(* Logix 5000 project; controller NXFE2_EDS_AOI_sample_RSLogix_V31 vendor 1 type 14 code 92 rev 31.11; software revision 31.00; part 4 of 4 *)

ADD_ON_INSTRUCTION AMCI_NXFE2_Set_State   (* revision 1.0, vendor AMCI, ExecuteEnableInFalse *)
VAR_INPUT
   axis_status_bits : INT; {required}
   No_Fault_Output_0_OFF_1_ON : BOOL; {required}
   On_Line_Output_0_OFF_1_ON : BOOL; {required}
   Move_Complete_Output_0_OFF_1_ON : BOOL; {required}
END_VAR
VAR_IN_OUT
   NXFE2_output_data : _000A:NXFE2_0986AEB4:O:0; {required}
END_VAR
VAR_OUTPUT
   EN : BOOL; {access Read Only, visible}
   ER : BOOL; {access Read Only, visible}
END_VAR
VAR
   command_data_block : INT[10];
        [1]   // Command Bits LSW
        [3]   // Lower Target Position
        [5]   // Lower Programmed Speed
        [1].5   // set state bit
        [0]   // Command Bits MSW
        [2]   // Upper Target Position
        [4]   // Upper Programmed Speed
END_VAR

ROUTINE EnableInFalse   (* ladder *)
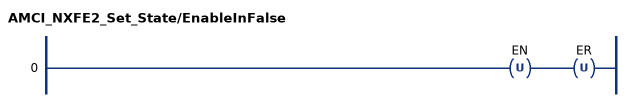
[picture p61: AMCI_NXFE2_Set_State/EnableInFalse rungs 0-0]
   0: OTU(EN)OTU(ER);
END_ROUTINE

ROUTINE Logic   (* ladder *)
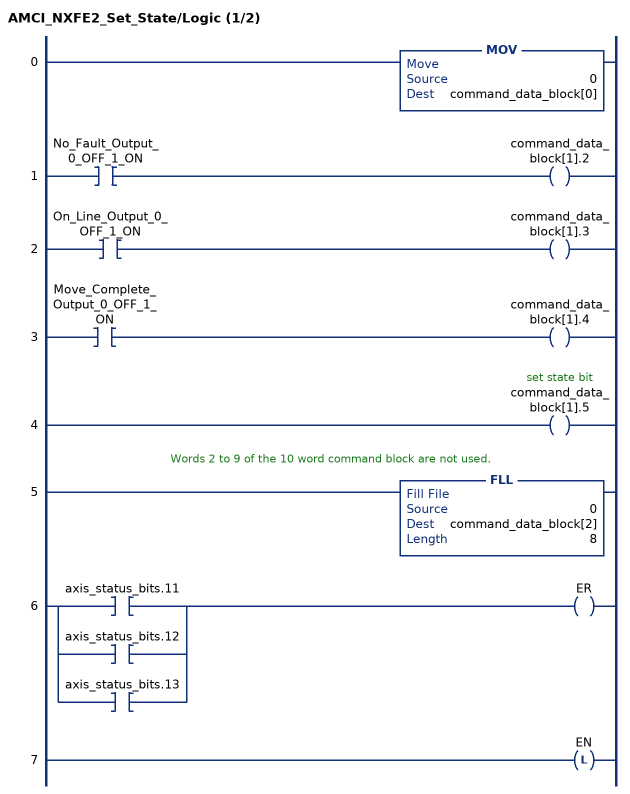
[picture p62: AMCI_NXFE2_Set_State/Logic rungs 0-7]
   0: MOV(0,command_data_block[0]);
   1: XIC(No_Fault_Output_0_OFF_1_ON)OTE(command_data_block[1].2);
   2: XIC(On_Line_Output_0_OFF_1_ON)OTE(command_data_block[1].3);
   3: XIC(Move_Complete_Output_0_OFF_1_ON)OTE(command_data_block[1].4);
   4: OTE(command_data_block[1].5);
   // Words 2 to 9 of the 10 word command block are not used.
   5: FLL(0,command_data_block[2],8);
   6: [XIC(axis_status_bits.11) ,XIC(axis_status_bits.12) ,XIC(axis_status_bits.13) ]OTE(ER);
   7: OTL(EN);
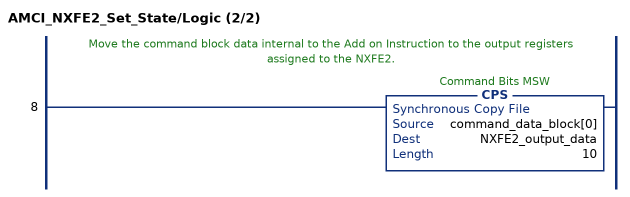
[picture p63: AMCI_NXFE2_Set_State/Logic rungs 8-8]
   // Move the command block data internal to the Add on Instruction to the output registers assigned to the NXFE2.
   8: CPS(command_data_block[0],NXFE2_output_data,10);
END_ROUTINE
END_ADD_ON_INSTRUCTION

VAR_GLOBAL   (* controller tags *)
   buffered_NXFE2_data : INT[10];
        [0].9   // set when the SD17060E is ready to receive a blend move segment
        [0].14   // AMCI ANG1E OK bit
        [0].15   // AMCI NXFE2 mode bit 1=config mode 0=command mode
        [1].15   // AMCI ANG1E set when driver enabled
        [0].0   // AMCI ANG1E motion occuring CW
        [0].1   // AMCI ANG1E motion occuring CCW
        [0].7   // ANG1E Move Compete bit
        [0].8   // set when SD17060E is in blend move mode
        [1].7   // AMCI ANG1E set when driver fault
        [0].10   // AMCI NXFE2 position invalid bit
        [0].13   // AMCI NXFE2 configuration error
   comment : INT;   // used as output instruction on comment rungs
   NXFE2_Communication_Status : INT;
   run_NXFE2 : INT;   // 1=absolute move 2=relative move 3=CW jog 4=CCW jog 5=Reset errors 6=Home CW 7=Preset Position 8=Program Blend 9=Run Blend
END_VAR

PROGRAM MainProgram   (* main routine MainRoutine *)
VAR
   AMCI_NXFE2_Set_State_AOI : AMCI_NXFE2_Set_State;
   NXFE2_Absolute_AOI : AMCI_NXFE2_Absolute_Move;
   NXFE2_Absolute_Move_AOI : AMCI_NXFE2_Absolute_Move;
   NXFE2_Configure_AOI : AMCI_NXFE2_Configure;
   NXFE2_encoder_follower_CCW : AMCI_NXFE2_Encoder_Follower_CCW;
   NXFE2_encoder_follower_CW : AMCI_NXFE2_Encoder_Follower_CW;
   NXFE2_Hold_AOI : AMCI_NXFE2_Hold;
   NXFE2_Home_CCW_AOI : AMCI_NXFE2_Home_CCW;
   NXFE2_Home_CW_AOI : AMCI_NXFE2_Home_CW;
   NXFE2_Immediate_Stop_AOI : AMCI_NXFE2_Immediate_Stop;
   NXFE2_Jog_CCW_AOI : AMCI_NXFE2_Jog_CCW;
   NXFE2_Jog_CW_AOI : AMCI_NXFE2_Jog_CW;
   NXFE2_Min_Registration_Distance_AOI : AMCI_NXFE2_Minimum_Registration_Distance;
   NXFE2_Preset_encoder_AOI : AMCI_NXFE2_Preset_Encoder_Position;
   NXFE2_Preset_Position_AOI : AMCI_NXFE2_Preset_Position;
   NXFE2_Program_Blend_AOI : AMCI_NXFE2_Program_Blend_Move;
   NXFE2_Registration_CCW_AOI : AMCI_NXFE2_Registration_Move_CCW;
   NXFE2_Registration_CW_AOI : AMCI_NXFE2_Registration_Move_CW;
   NXFE2_Relative_Move_AOI : AMCI_NXFE2_Relative_Move;
   NXFE2_Reset_Errors_AOI : AMCI_NXFE2_Reset_Errors;
   NXFE2_Resume_AOI : AMCI_NXFE2_Resume;
   NXFE2_Run_Blend : AMCI_NXFE2_Run_Blend_Move;
END_VAR

ROUTINE Blend_Move   (* ladder *)
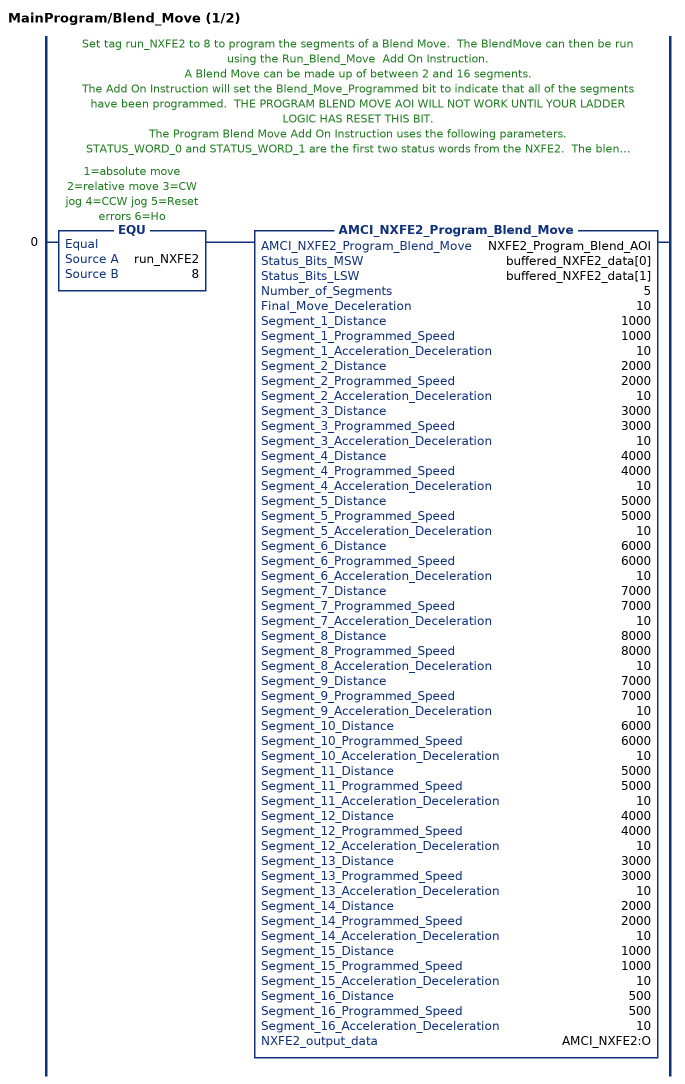
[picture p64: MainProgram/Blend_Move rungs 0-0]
   // Set tag run_NXFE2 to 8 to program the segments of a Blend Move.  The BlendMove can then be run using the Run_Blend_Move  Add On Instruction.
   // A Blend Move can be made up of between 2 and 16 segments.
   // The Add On Instruction will set the Blend_Move_Programmed bit to indicate that all of the segments have been programmed.  THE PROGRAM BLEND MOVE AOI WILL NOT WORK UNTIL YOUR LADDER LOGIC HAS RESET THIS BIT.
   // The Program Blend Move Add On Instruction uses the following parameters.
   // STATUS_WORD_0 and STATUS_WORD_1 are the first two status words from the NXFE2.  The blend move will not be correctly programmed if these two status words are not correctly brought into the program blend add on instruction.
   // NUMBER OF SEGMENTS: An actual value or an INT type register that has a range of 2 to 16 and specifies the number of segments of the Blend Move.
   // SEGMENT_X_DISTANCE: An actual value or a DINT type register.  The relative distance of each of the Blend Move Segments.
   // SEGMENT_X_PROGRAMMED_SPEED: An actual value or a DINT type register.  The running speed of each of the programmed segments.
   // SEGMENT_X_ACCELERATION_DECELERATION: An actual value or an INT type register that defines how fast the speed of one segment will change to the speed of another segment.
   // BOOL BLEND_MOVE_Programmed bit indicates when all of the segments have been programmed.
   // Register run_NXFE2 is only an internal tag used to illustrate how the rung must go from false to true to make the move operation occur, and is set by either manually typing the number into the register or having your ladder logic move a value into the register.  IT IS NOT NECESSASRY TO USE THIS REGISTER OR AN EQUAL INSTRUCTION TO SEND COMMANDS TO THE AMCI NXFE2.  You can replace it with any other condition that makes the rung true, such as a push button on a HMI terminal.
   0: EQU(run_NXFE2,8)AMCI_NXFE2_Program_Blend_Move(NXFE2_Program_Blend_AOI,buffered_NXFE2_data[0],buffered_NXFE2_data[1],5,10,1000,1000,10,2000,2000,10,3000,3000,10,4000,4000,10,5000,5000,10,6000,6000,10,7000,7000,10,8000,8000,10,7000,7000,10,6000,6000,10,5000,5000,10,4000,4000,10,3000,3000,10,2000,2000,10,1000,1000,10,500,500,10,AMCI_NXFE2:O);
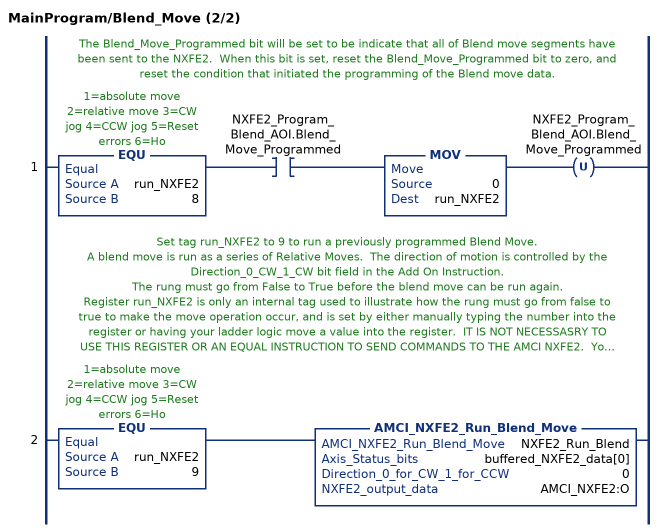
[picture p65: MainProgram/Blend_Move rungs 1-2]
   // The Blend_Move_Programmed bit will be set to be indicate that all of Blend move segments have been sent to the NXFE2.  When this bit is set, reset the Blend_Move_Programmed bit to zero, and reset the condition that initiated the programming of the Blend move data.
   1: EQU(run_NXFE2,8)XIC(NXFE2_Program_Blend_AOI.Blend_Move_Programmed)MOV(0,run_NXFE2)OTU(NXFE2_Program_Blend_AOI.Blend_Move_Programmed);
   // Set tag run_NXFE2 to 9 to run a previously programmed Blend Move.
   // A blend move is run as a series of Relative Moves.  The direction of motion is controlled by the Direction_0_CW_1_CW bit field in the Add On Instruction.
   // The rung must go from False to True before the blend move can be run again.
   // Register run_NXFE2 is only an internal tag used to illustrate how the rung must go from false to true to make the move operation occur, and is set by either manually typing the number into the register or having your ladder logic move a value into the register.  IT IS NOT NECESSASRY TO USE THIS REGISTER OR AN EQUAL INSTRUCTION TO SEND COMMANDS TO THE AMCI NXFE2.  You can replace it with any other condition that makes the rung true, such as a push button on a HMI terminal.
   2: EQU(run_NXFE2,9)AMCI_NXFE2_Run_Blend_Move(NXFE2_Run_Blend,buffered_NXFE2_data[0],0,AMCI_NXFE2:O);
END_ROUTINE

ROUTINE MainRoutine   (* ladder *)
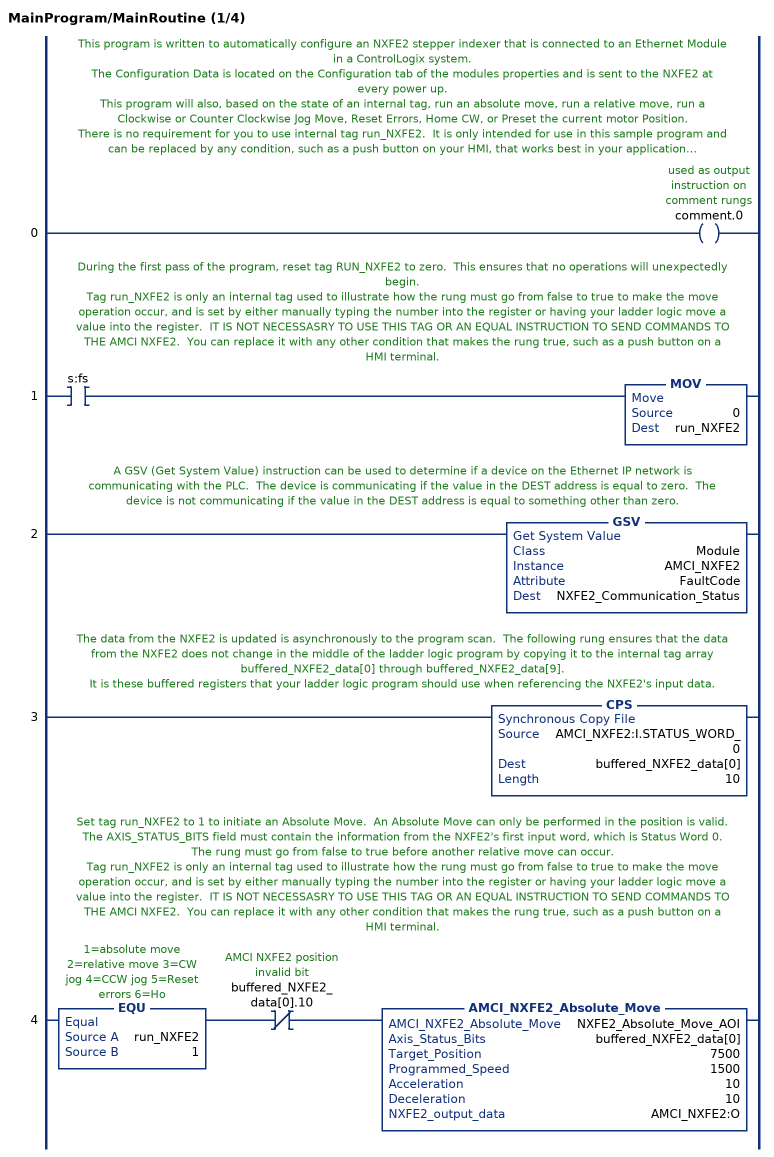
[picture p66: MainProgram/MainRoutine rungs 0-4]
   // This program is written to automatically configure an NXFE2 stepper indexer that is connected to an Ethernet Module in a ControlLogix system.
   // The Configuration Data is located on the Configuration tab of the modules properties and is sent to the NXFE2 at every power up.
   // This program will also, based on the state of an internal tag, run an absolute move, run a relative move, run a Clockwise or Counter Clockwise Jog Move, Reset Errors, Home CW, or Preset the current motor Position.
   // There is no requirement for you to use internal tag run_NXFE2.  It is only intended for use in this sample program and can be replaced by any condition, such as a push button on your HMI, that works best in your application.
   // CPS instructions are used in place of COP instructions to ensure that the transfer of data from the PLC to the NXFE2 is not interrupted by RPI I/O update of the NXFE2.
   // This program also uses Add On Instructions for most of the NXFE2's functions.  These instructions prompt you for what data is required for the requested move operation, and set / reset the appropriate control bits and words.
   // The NXFE2 was added to the Ethernet network using an EDS file.  The Add On instructions used in this sample program are based on the tags created by the EDS file.
   // Some of the Add On Instructions have some of the less commonly used functions, such as acceleration type, hidden.   The Add On Instructions are not locked or protected and, if desired, these functions can be made visible and enabled.
   // Most of the Add On Instructions have an input field called AXIS_STATUS_BITS.  This field must be set to the NXFE2's STATUS_WORD_0.   Some of the functions of the Add On Instruction will not be available if the Axis_Status_bits field remains equal to zero.
   // This sample program has a subroutine that explains and shows the use of one of the more complex Add On Instructions, Program Blend_Move.  Ignore or delete this subroutine if you are not using the blend move function.
   0: OTE(comment.0);
   // During the first pass of the program, reset tag RUN_NXFE2 to zero.  This ensures that no operations will unexpectedly begin.
   // Tag run_NXFE2 is only an internal tag used to illustrate how the rung must go from false to true to make the move operation occur, and is set by either manually typing the number into the register or having your ladder logic move a value into the register.  IT IS NOT NECESSASRY TO USE THIS TAG OR AN EQUAL INSTRUCTION TO SEND COMMANDS TO THE AMCI NXFE2.  You can replace it with any other condition that makes the rung true, such as a push button on a HMI terminal.
   1: XIC(s:fs)MOV(0,run_NXFE2);
   // A GSV (Get System Value) instruction can be used to determine if a device on the Ethernet IP network is communicating with the PLC.  The device is communicating if the value in the DEST address is equal to zero.  The device is not communicating if the value in the DEST address is equal to something other than zero.
   2: GSV(Module,AMCI_NXFE2,FaultCode,NXFE2_Communication_Status);
   // The data from the NXFE2 is updated is asynchronously to the program scan.  The following rung ensures that the data from the NXFE2 does not change in the middle of the ladder logic program by copying it to the internal tag array buffered_NXFE2_data[0] through buffered_NXFE2_data[9].
   // It is these buffered registers that your ladder logic program should use when referencing the NXFE2's input data.
   3: CPS(AMCI_NXFE2:I.STATUS_WORD_0,buffered_NXFE2_data[0],10);
   // Set tag run_NXFE2 to 1 to initiate an Absolute Move.  An Absolute Move can only be performed in the position is valid.
   // The AXIS_STATUS_BITS field must contain the information from the NXFE2's first input word, which is Status Word 0.
   // The rung must go from false to true before another relative move can occur.
   // Tag run_NXFE2 is only an internal tag used to illustrate how the rung must go from false to true to make the move operation occur, and is set by either manually typing the number into the register or having your ladder logic move a value into the register.  IT IS NOT NECESSASRY TO USE THIS TAG OR AN EQUAL INSTRUCTION TO SEND COMMANDS TO THE AMCI NXFE2.  You can replace it with any other condition that makes the rung true, such as a push button on a HMI terminal.
   4: EQU(run_NXFE2,1)XIO(buffered_NXFE2_data[0].10)AMCI_NXFE2_Absolute_Move(NXFE2_Absolute_Move_AOI,buffered_NXFE2_data[0],7500,1500,10,10,AMCI_NXFE2:O);
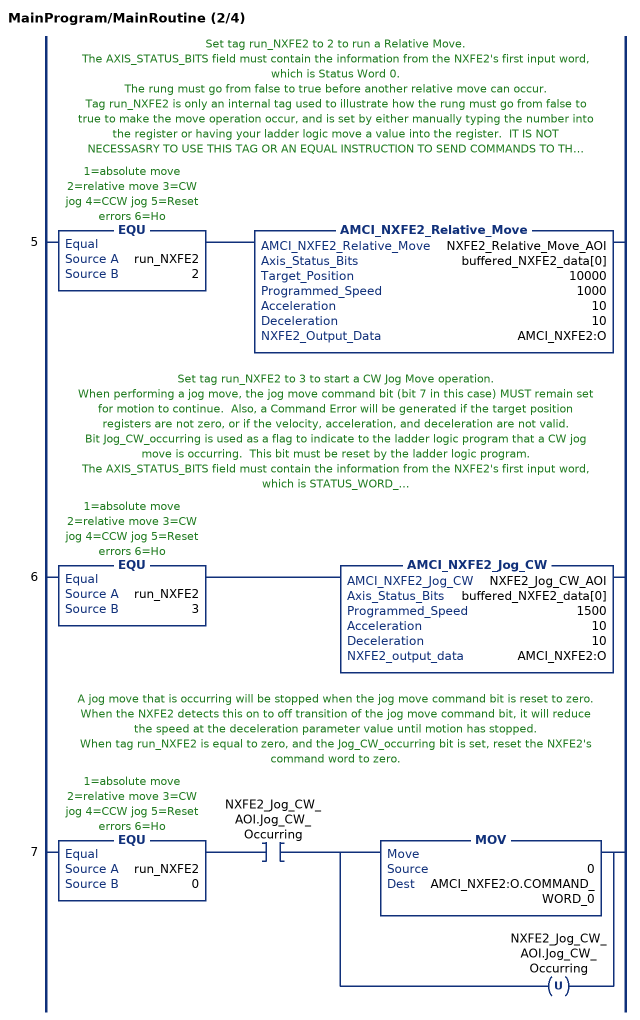
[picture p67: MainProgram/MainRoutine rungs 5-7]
   // Set tag run_NXFE2 to 2 to run a Relative Move.
   // The AXIS_STATUS_BITS field must contain the information from the NXFE2's first input word, which is Status Word 0.
   // The rung must go from false to true before another relative move can occur.
   // Tag run_NXFE2 is only an internal tag used to illustrate how the rung must go from false to true to make the move operation occur, and is set by either manually typing the number into the register or having your ladder logic move a value into the register.  IT IS NOT NECESSASRY TO USE THIS TAG OR AN EQUAL INSTRUCTION TO SEND COMMANDS TO THE AMCI NXFE2.  You can replace it with any other condition that makes the rung true, such as a push button on a HMI terminal.
   5: EQU(run_NXFE2,2)AMCI_NXFE2_Relative_Move(NXFE2_Relative_Move_AOI,buffered_NXFE2_data[0],10000,1000,10,10,AMCI_NXFE2:O);
   // Set tag run_NXFE2 to 3 to start a CW Jog Move operation.
   // When performing a jog move, the jog move command bit (bit 7 in this case) MUST remain set for motion to continue.  Also, a Command Error will be generated if the target position registers are not zero, or if the velocity, acceleration, and deceleration are not valid.
   // Bit Jog_CW_occurring is used as a flag to indicate to the ladder logic program that a CW jog move is occurring.  This bit must be reset by the ladder logic program.
   // The AXIS_STATUS_BITS field must contain the information from the NXFE2's first input word, which is STATUS_WORD_0
   // Tag run_NXFE2 is only an internal tag used to illustrate how the rung must go from false to true to make the move operation occur, and is set by either manually typing the number into the register or having your ladder logic move a value into the register.  IT IS NOT NECESSASRY TO USE THIS TAG OR AN EQUAL INSTRUCTION TO SEND COMMANDS TO THE AMCI NXFE2.  You can replace it with any other condition that makes the rung true, such as a push button on a HMI terminal.
   6: EQU(run_NXFE2,3)AMCI_NXFE2_Jog_CW(NXFE2_Jog_CW_AOI,buffered_NXFE2_data[0],1500,10,10,AMCI_NXFE2:O);
   // A jog move that is occurring will be stopped when the jog move command bit is reset to zero.  When the NXFE2 detects this on to off transition of the jog move command bit, it will reduce the speed at the deceleration parameter value until motion has stopped.
   // When tag run_NXFE2 is equal to zero, and the Jog_CW_occurring bit is set, reset the NXFE2's command word to zero.
   7: EQU(run_NXFE2,0)XIC(NXFE2_Jog_CW_AOI.Jog_CW_Occurring)[MOV(0,AMCI_NXFE2:O.COMMAND_WORD_0) ,OTU(NXFE2_Jog_CW_AOI.Jog_CW_Occurring) ];
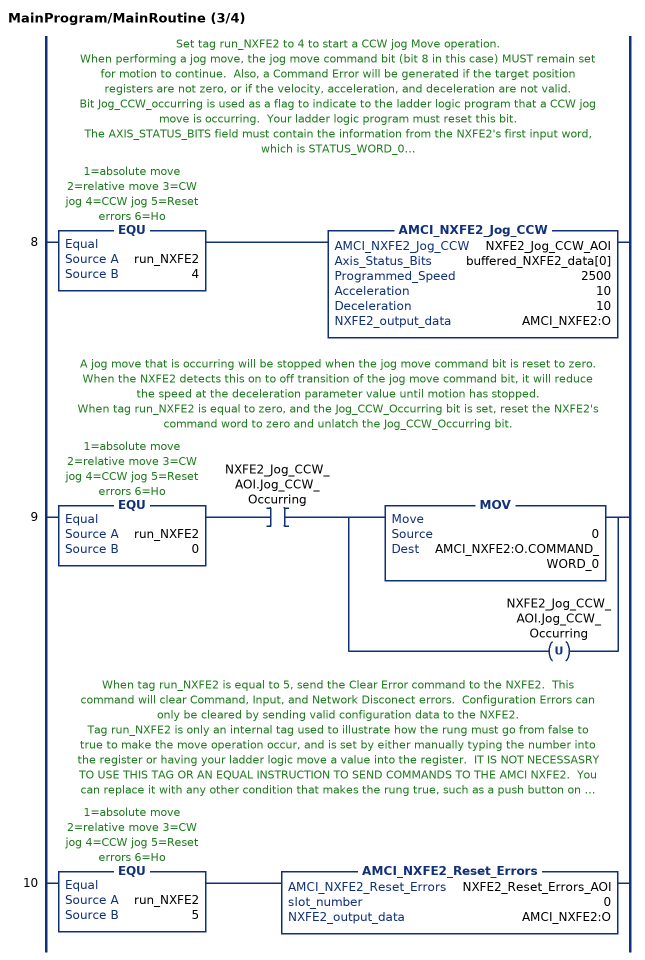
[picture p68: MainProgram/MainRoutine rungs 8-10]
   // Set tag run_NXFE2 to 4 to start a CCW jog Move operation.
   // When performing a jog move, the jog move command bit (bit 8 in this case) MUST remain set for motion to continue.  Also, a Command Error will be generated if the target position registers are not zero, or if the velocity, acceleration, and deceleration are not valid.
   // Bit Jog_CCW_occurring is used as a flag to indicate to the ladder logic program that a CCW jog move is occurring.  Your ladder logic program must reset this bit.
   // The AXIS_STATUS_BITS field must contain the information from the NXFE2's first input word, which is STATUS_WORD_0.
   // Tag run_NXFE2 is only an internal tag used to illustrate how the rung must go from false to true to make the move operation occur, and is set by either manually typing the number into the register or having your ladder logic move a value into the register.  IT IS NOT NECESSASRY TO USE THIS TAG OR AN EQUAL INSTRUCTION TO SEND COMMANDS TO THE AMCI NXFE2.  You can replace it with any other condition that makes the rung true, such as a push button on a HMI terminal.
   8: EQU(run_NXFE2,4)AMCI_NXFE2_Jog_CCW(NXFE2_Jog_CCW_AOI,buffered_NXFE2_data[0],2500,10,10,AMCI_NXFE2:O);
   // A jog move that is occurring will be stopped when the jog move command bit is reset to zero.  When the NXFE2 detects this on to off transition of the jog move command bit, it will reduce the speed at the deceleration parameter value until motion has stopped.
   // When tag run_NXFE2 is equal to zero, and the Jog_CCW_Occurring bit is set, reset the NXFE2's command word to zero and unlatch the Jog_CCW_Occurring bit.
   9: EQU(run_NXFE2,0)XIC(NXFE2_Jog_CCW_AOI.Jog_CCW_Occurring)[MOV(0,AMCI_NXFE2:O.COMMAND_WORD_0) ,OTU(NXFE2_Jog_CCW_AOI.Jog_CCW_Occurring) ];
   // When tag run_NXFE2 is equal to 5, send the Clear Error command to the NXFE2.  This command will clear Command, Input, and Network Disconect errors.  Configuration Errors can only be cleared by sending valid configuration data to the NXFE2.
   // Tag run_NXFE2 is only an internal tag used to illustrate how the rung must go from false to true to make the move operation occur, and is set by either manually typing the number into the register or having your ladder logic move a value into the register.  IT IS NOT NECESSASRY TO USE THIS TAG OR AN EQUAL INSTRUCTION TO SEND COMMANDS TO THE AMCI NXFE2.  You can replace it with any other condition that makes the rung true, such as a push button on a HMI terminal.
   10: EQU(run_NXFE2,5)AMCI_NXFE2_Reset_Errors(NXFE2_Reset_Errors_AOI,0,AMCI_NXFE2:O);
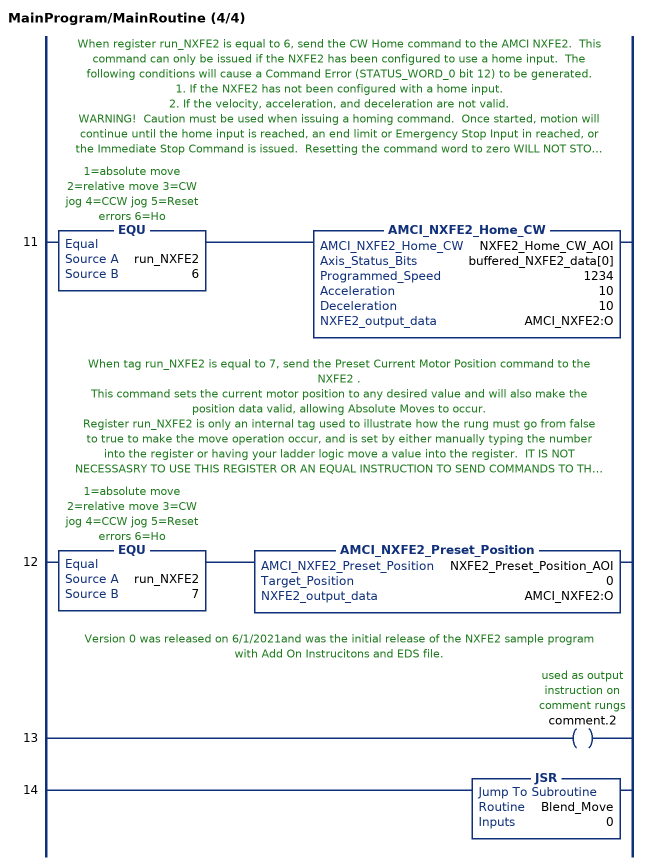
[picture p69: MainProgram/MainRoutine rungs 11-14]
   // When register run_NXFE2 is equal to 6, send the CW Home command to the AMCI NXFE2.  This command can only be issued if the NXFE2 has been configured to use a home input.  The following conditions will cause a Command Error (STATUS_WORD_0 bit 12) to be generated.
   // 1. If the NXFE2 has not been configured with a home input.
   // 2. If the velocity, acceleration, and deceleration are not valid.
   // WARNING!  Caution must be used when issuing a homing command.  Once started, motion will continue until the home input is reached, an end limit or Emergency Stop Input in reached, or the Immediate Stop Command is issued.  Resetting the command word to zero WILL NOT STOP a home operation.
   // The AXIS_STATUS_BITS field must contain the information from the NXFE2's first input word, which is Status STATUS_WORD_0.
   // Register run_NXFE2 is only an internal tag used to illustrate how the rung must go from false to true to make the move operation occur, and is set by either manually typing the number into the register or having your ladder logic move a value into the register.  IT IS NOT NECESSASRY TO USE THIS REGISTER OR AN EQUAL INSTRUCTION TO SEND COMMANDS TO THE AMCI NXFE2.  You can replace it with any other condition that makes the rung true, such as a push button on a HMI terminal.
   11: EQU(run_NXFE2,6)AMCI_NXFE2_Home_CW(NXFE2_Home_CW_AOI,buffered_NXFE2_data[0],1234,10,10,AMCI_NXFE2:O);
   // When tag run_NXFE2 is equal to 7, send the Preset Current Motor Position command to the NXFE2 .
   // This command sets the current motor position to any desired value and will also make the position data valid, allowing Absolute Moves to occur.
   // Register run_NXFE2 is only an internal tag used to illustrate how the rung must go from false to true to make the move operation occur, and is set by either manually typing the number into the register or having your ladder logic move a value into the register.  IT IS NOT NECESSASRY TO USE THIS REGISTER OR AN EQUAL INSTRUCTION TO SEND COMMANDS TO THE AMCI NXFE2.  You can replace it with any other condition that makes the rung true, such as a push button on a HMI terminal.
   12: EQU(run_NXFE2,7)AMCI_NXFE2_Preset_Position(NXFE2_Preset_Position_AOI,0,AMCI_NXFE2:O);
   // Version 0 was released on 6/1/2021and was the initial release of the NXFE2 sample program with Add On Instrucitons and EDS file.
   13: OTE(comment.2);
   14: JSR(Blend_Move,0);
END_ROUTINE
END_PROGRAM
